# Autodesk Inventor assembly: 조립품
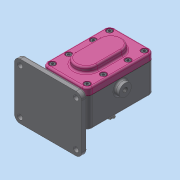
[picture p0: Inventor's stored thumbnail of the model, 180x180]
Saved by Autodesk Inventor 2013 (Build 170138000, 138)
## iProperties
Created: 2020-04
Part Number: 조립품
Document SubType Name: Assembly
Designer: dgall
Author: dgall
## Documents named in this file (11)
- C:\Users\dgall\Desktop\700407V1032\조립품.iam
- C:\Users\dgall\Desktop\700407V1032\본체.ipt
- C:\Users\dgall\Desktop\700407V1032\메인축.ipt
- C:\Users\dgall\Desktop\700407V1032\오일 실 16 28 7.ipt
- C:\Users\dgall\Desktop\700407V1032\베어링부시.ipt
- C:\Users\dgall\Desktop\700407V1032\스퍼기어.ipt
- C:\Users\dgall\Desktop\700407V1032\키 6 x 6 x 18.ipt
- C:\Users\dgall\Desktop\700407V1032\서브축.ipt
- C:\Users\dgall\Desktop\700407V1032\커버.ipt
- C:\Users\dgall\Desktop\700407V1032\볼트 M5.ipt
- C:\Users\dgall\Desktop\700407V1032\개스킷.ipt
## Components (1 placed, 1 different names)
1. 개스킷:1
